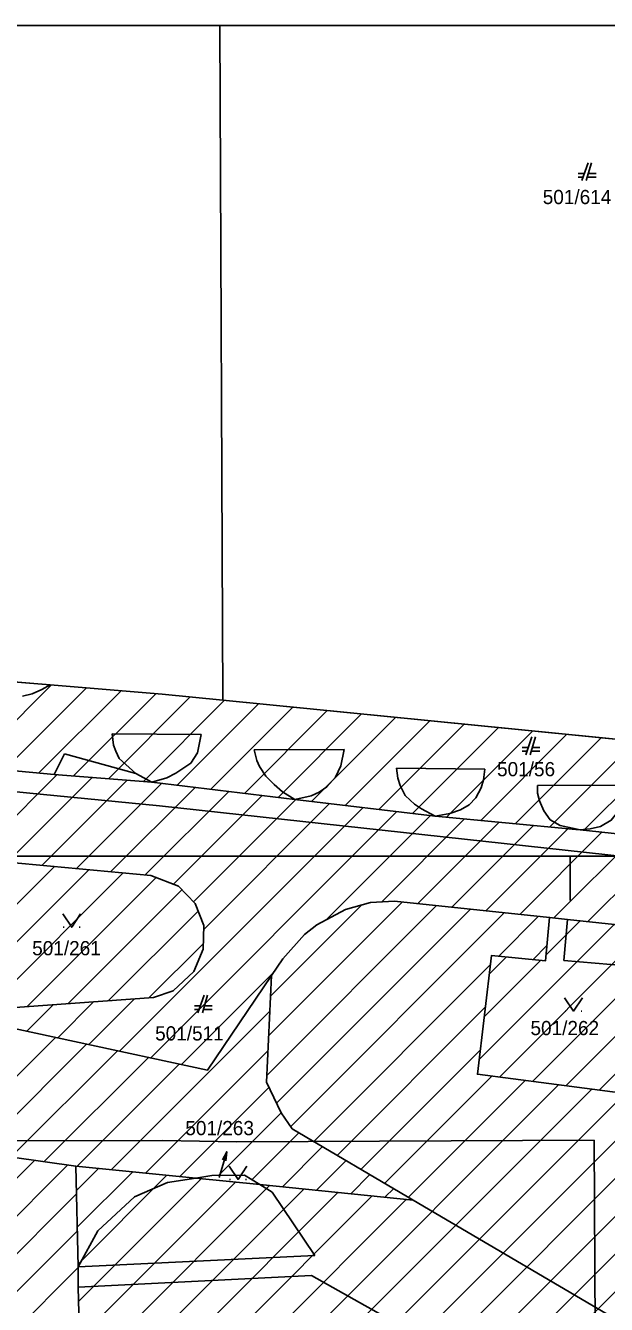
# Model space of a CAD drawing. Extents: x -264309 to -263505, y -1242443 to -1241763.
# Drawn here: x -263852.2 to -263786.7, y -1242101 to -1241957 of the extents above; entities that cross this region are included whole.
import ezdxf

# ---------------------------------------------------------------- set-up
doc = ezdxf.new("R2010")
doc.units = 0
for name, color, linetype in [('KFA_SO_50-2_POZIARNY_VODOVOD_TRASA', 7, 'Continuous'), ('KN_2019_08_16_KLADPAR', 7, 'Continuous'), ('KN_2019_08_16_ZAPPAR', 7, 'Continuous'), ('RAM_NA_TLAC_10xA4_1-500', 7, 'Continuous'), ('SRAFY_PARCELY', 7, 'Continuous')]:
    doc.layers.add(name, color=color, linetype=linetype)

msp = doc.modelspace()

# ---------------------------------------------------------------- linework, layer by layer
at = {"layer": 'KFA_SO_50-2_POZIARNY_VODOVOD_TRASA'}
msp.add_lwpolyline([(-263924.93, -1242185.13), (-263924.15, -1242197.09), (-263924.3, -1242220.9), (-263924.1, -1242250.12), (-263913.99, -1242249.8), (-263886.91, -1242249.88), (-263867.71, -1242249.83), (-263837.26, -1242249.84), (-263828.16, -1242249.9), (-263787.99, -1242250.03), (-263788.2, -1242220.84), (-263788.2, -1242200.51), (-263788.09, -1242179.92), (-263788.06, -1242148.96), (-263787.92, -1242127.95), (-263787.95, -1242110.97), (-263788.13, -1242082.54), (-263828.43, -1242082.72), (-263836.78, -1242082.56), (-263867.31, -1242082.61), (-263886.71, -1242082.47), (-263924.08, -1242082.61), (-263924.64, -1242106.32), (-263924.48, -1242117.43)], close=True, dxfattribs=at)
at = {"layer": 'KN_2019_08_16_KLADPAR'}
for p, q in [((-263914.3, -1241956.96), (-263830.29, -1241956.96)), ((-263830.29, -1241956.96), (-263829.96, -1242032.95)), ((-263830.29, -1241956.96), (-263745.67, -1241956.96)), ((-263829.96, -1242032.95), (-263830.29, -1241956.96)), ((-263788.8, -1241972.42), (-263789.5, -1241974.42)), ((-263789, -1241974.42), (-263788.4, -1241972.42)), ((-263789.22, -1241973.62), (-263789.9, -1241973.62)), ((-263789.9, -1241974.02), (-263789.36, -1241974.02)), ((-263788.88, -1241974.02), (-263787.9, -1241974.02)), ((-263787.9, -1241973.62), (-263788.76, -1241973.62)), ((-263849.43, -1242031.23), (-263857.26, -1242030.58)), ((-263836.79, -1242032.27), (-263849.43, -1242031.23)), ((-263829.96, -1242032.95), (-263836.79, -1242032.27)), ((-263750.04, -1242040.89), (-263829.96, -1242032.95)), ((-263795.54, -1242038.3), (-263796.22, -1242038.3)), ((-263795.12, -1242037.1), (-263795.82, -1242039.1)), ((-263795.32, -1242039.1), (-263794.72, -1242037.1)), ((-263794.22, -1242038.3), (-263795.08, -1242038.3)), ((-263796.22, -1242038.7), (-263795.68, -1242038.7)), ((-263795.2, -1242038.7), (-263794.22, -1242038.7)), ((-263847.95, -1242058.55), (-263847.85, -1242058.55)), ((-263846.15, -1242058.55), (-263846.05, -1242058.55)), ((-263832.08, -1242066.2), (-263832.78, -1242068.2)), ((-263832.28, -1242068.2), (-263831.68, -1242066.2)), ((-263832.5, -1242067.4), (-263833.18, -1242067.4)), ((-263833.18, -1242067.8), (-263832.64, -1242067.8)), ((-263832.16, -1242067.8), (-263831.18, -1242067.8)), ((-263831.18, -1242067.4), (-263832.04, -1242067.4)), ((-263791.39, -1242067.99), (-263791.29, -1242067.99)), ((-263789.59, -1242067.99), (-263789.49, -1242067.99)), ((-263830, -1242084.75), (-263829.53, -1242083.84)), ((-263829.2, -1242086.95), (-263829.1, -1242086.95)), ((-263827.4, -1242086.95), (-263827.3, -1242086.95))]:
    msp.add_line(p, q, dxfattribs=at)
for points in [[(-263773.94, -1242049.27), (-263789.68, -1242047.57), (-263790.18, -1242047.53), (-263806.03, -1242046.03), (-263821.84, -1242044.14), (-263837.98, -1242042.2), (-263848.99, -1242041.32), (-263854.22, -1242040.83), (-263895.14, -1242037.44), (-263924.96, -1242034.66), (-263926.48, -1242034.52), (-263943.42, -1242032.17), (-263943.43, -1242031.76), (-263943.61, -1242023.45), (-263914.84, -1242025.82), (-263914, -1242025.89), (-263874.62, -1242029.15), (-263857.26, -1242030.58), (-263849.43, -1242031.23), (-263836.79, -1242032.27), (-263829.96, -1242032.95), (-263750.04, -1242040.89)], [(-263970.71, -1242028.65), (-263951.74, -1242030.76), (-263946.18, -1242031.43), (-263943.43, -1242031.76), (-263943.42, -1242032.17), (-263926.48, -1242034.52), (-263924.96, -1242034.66), (-263895.14, -1242037.44), (-263854.22, -1242040.83), (-263848.99, -1242041.32), (-263837.98, -1242042.2), (-263821.84, -1242044.14), (-263806.03, -1242046.03), (-263790.18, -1242047.53), (-263789.68, -1242047.57), (-263773.94, -1242049.27)], [(-263784.04, -1242058.41), (-263791.13, -1242057.66), (-263793.14, -1242057.44), (-263810.6, -1242055.59), (-263813.32, -1242055.74), (-263816.16, -1242056.54), (-263819.37, -1242058.28), (-263820.78, -1242059.35), (-263823.22, -1242062.1), (-263824.48, -1242063.97), (-263831.68, -1242074.63), (-263861.71, -1242068.19), (-263837.8, -1242066.47), (-263835.57, -1242065.69), (-263833.22, -1242063.52), (-263832.17, -1242061), (-263832.11, -1242058.36), (-263833.09, -1242055.88), (-263834.98, -1242053.91), (-263838.09, -1242052.7), (-263860.75, -1242050.61)], [(-263845.63, -1242123.54), (-263846.29, -1242099.09), (-263846.27, -1242096.79), (-263846.54, -1242085.45), (-263833.02, -1242086.81), (-263825.79, -1242087.54), (-263808.5, -1242089.28), (-263822.15, -1242081.25), (-263823.41, -1242079.44), (-263825.06, -1242076), (-263824.48, -1242063.97), (-263823.22, -1242062.1), (-263820.78, -1242059.35), (-263819.37, -1242058.28), (-263816.16, -1242056.54), (-263813.32, -1242055.74), (-263810.6, -1242055.59), (-263793.14, -1242057.44), (-263793.59, -1242062.32), (-263799.68, -1242061.72), (-263801.28, -1242075.1), (-263785.17, -1242077.19)], [(-263848, -1242057.05), (-263847, -1242058.55), (-263846, -1242057.05)], [(-263791.44, -1242066.49), (-263790.44, -1242067.99), (-263789.44, -1242066.49)], [(-263830.38, -1242086.72), (-263829.53, -1242083.84), (-263829.62, -1242084.86)], [(-263829.25, -1242085.45), (-263828.25, -1242086.95), (-263827.25, -1242085.45)]]:
    msp.add_lwpolyline(points, dxfattribs=at)
for points in [[(-263860.75, -1242050.61), (-263838.09, -1242052.7), (-263834.98, -1242053.91), (-263833.09, -1242055.88), (-263832.11, -1242058.36), (-263832.17, -1242061), (-263833.22, -1242063.52), (-263835.57, -1242065.69), (-263837.8, -1242066.47), (-263861.71, -1242068.19), (-263866.84, -1242068.34), (-263856.75, -1242052.73), (-263857.2, -1242052.16), (-263859.25, -1242051.26)], [(-263793.14, -1242057.44), (-263791.13, -1242057.66), (-263784.04, -1242058.41), (-263782.02, -1242058.63), (-263782.64, -1242063.41), (-263775.43, -1242063.83), (-263775.63, -1242071.05), (-263780.92, -1242070.3), (-263781.45, -1242072.38), (-263784.12, -1242072.3), (-263785.17, -1242077.19), (-263801.28, -1242075.1), (-263799.68, -1242061.72), (-263793.59, -1242062.32)], [(-263866.84, -1242068.34), (-263861.71, -1242068.19), (-263831.68, -1242074.63), (-263824.48, -1242063.97), (-263825.06, -1242076), (-263823.41, -1242079.44), (-263822.15, -1242081.25), (-263808.5, -1242089.28), (-263825.79, -1242087.54), (-263827.51, -1242086.49), (-263831.22, -1242086.53), (-263833.02, -1242086.81), (-263846.54, -1242085.45), (-263942.54, -1242071.9), (-263913.4, -1242070.43), (-263886.83, -1242069.14)], [(-263942.54, -1242071.9), (-263846.54, -1242085.45), (-263846.27, -1242096.79), (-263846.29, -1242099.09), (-263845.63, -1242123.54), (-263845.17, -1242145.54), (-263890.62, -1242146.65), (-263890.76, -1242147.37), (-263921.62, -1242147.75), (-263934.65, -1242147.91), (-263935.23, -1242123.81), (-263941.18, -1242123.7)], [(-263833.02, -1242086.81), (-263831.22, -1242086.53), (-263827.51, -1242086.49), (-263825.79, -1242087.54)]]:
    msp.add_lwpolyline(points, close=True, dxfattribs=at)
at = {"layer": 'KN_2019_08_16_ZAPPAR'}
for p, q in [((-263842.44, -1242036.74), (-263832.41, -1242036.83)), ((-263848.99, -1242041.32), (-263847.83, -1242039)), ((-263847.83, -1242039), (-263839.79, -1242041.23)), ((-263826.44, -1242038.56), (-263816.28, -1242038.5)), ((-263810.4, -1242040.62), (-263800.44, -1242040.72)), ((-263794.51, -1242042.59), (-263784.38, -1242042.55)), ((-263837.1, -1242044.85), (-263784.51, -1242050.62)), ((-263791.13, -1242057.66), (-263791.54, -1242062.3)), ((-263791.54, -1242062.3), (-263784.47, -1242062.88)), ((-263844.07, -1242092.73), (-263839.91, -1242088.93)), ((-263808.5, -1242089.28), (-263779.5, -1242106.34)), ((-263846.27, -1242096.79), (-263844.07, -1242092.73)), ((-263819.59, -1242095.53), (-263846.27, -1242096.79))]:
    msp.add_line(p, q, dxfattribs=at)
for points in [[(-264009.05, -1242025.11), (-264007.06, -1242027.03), (-264004.88, -1242027.82), (-264001.52, -1242027.99), (-263958.32, -1242033), (-263951.68, -1242033.75), (-263943.48, -1242034.79), (-263940.72, -1242035.02), (-263926.91, -1242036.98), (-263897.04, -1242039.59), (-263857.13, -1242042.91), (-263837.1, -1242044.85)], [(-263849.43, -1242031.23), (-263850.37, -1242031.77), (-263851.47, -1242032.24), (-263852.57, -1242032.52)], [(-263839.79, -1242041.23), (-263841.67, -1242039.55), (-263842.02, -1242038.7), (-263842.29, -1242038.02), (-263842.44, -1242036.74)], [(-263832.41, -1242036.83), (-263832.83, -1242038.89), (-263833.57, -1242040.05), (-263835.28, -1242041.18), (-263836.28, -1242041.7), (-263837.98, -1242042.2), (-263839.79, -1242041.23)], [(-263821.84, -1242044.14), (-263823.25, -1242043.3), (-263824.18, -1242042.46), (-263825.11, -1242041.53), (-263825.82, -1242040.45), (-263826.13, -1242039.75), (-263826.44, -1242038.56)], [(-263816.28, -1242038.5), (-263816.67, -1242040.36), (-263817.26, -1242041.62), (-263818.26, -1242042.72), (-263819.1, -1242043.33), (-263820.01, -1242043.75), (-263821.84, -1242044.14)], [(-263800.44, -1242040.72), (-263800.6, -1242041.94), (-263800.86, -1242042.85), (-263801.46, -1242043.97), (-263802.2, -1242044.75), (-263803.16, -1242045.33), (-263804.37, -1242045.72), (-263806.03, -1242046.03), (-263807.58, -1242045.2), (-263808.35, -1242044.69), (-263808.86, -1242044.23), (-263809.41, -1242043.71), (-263809.99, -1242042.56), (-263810.25, -1242041.75), (-263810.4, -1242040.62)], [(-263789.68, -1242047.57), (-263791.94, -1242047.07), (-263793.07, -1242046.43), (-263793.8, -1242045.41), (-263794.29, -1242044.29), (-263794.49, -1242043.45), (-263794.51, -1242042.59)], [(-263784.38, -1242042.55), (-263784.64, -1242044.03), (-263785.09, -1242045.11), (-263786.18, -1242046.49), (-263787.4, -1242047.18), (-263788.56, -1242047.44), (-263789.68, -1242047.57)], [(-263839.91, -1242088.93), (-263836.21, -1242087.31), (-263833.02, -1242086.81)], [(-263825.79, -1242087.54), (-263824.41, -1242088.38), (-263819.59, -1242095.53)], [(-263846.29, -1242099.09), (-263819.98, -1242097.79), (-263807.62, -1242104.72), (-263808.64, -1242106.7), (-263804.15, -1242109.21), (-263803.06, -1242107.29)]]:
    msp.add_lwpolyline(points, dxfattribs=at)
at = {"layer": 'RAM_NA_TLAC_10xA4_1-500'}
msp.add_line((-263790.83, -1242050.54), (-263790.83, -1242055.54), dxfattribs=at)
msp.add_lwpolyline([(-264210.83, -1242050.54), (-264105.83, -1242050.54), (-264000.83, -1242050.54), (-263895.83, -1242050.54), (-263790.83, -1242050.54), (-263685.83, -1242050.54), (-263685.83, -1242199.04), (-263685.83, -1242347.54), (-263790.83, -1242347.54), (-263895.83, -1242347.54), (-264000.83, -1242347.54), (-264105.83, -1242347.54), (-264210.83, -1242347.54), (-264210.83, -1242199.04)], close=True, dxfattribs=at)
at = {"layer": 'SRAFY_PARCELY'}
for p, q in [((-263858.5, -1242040.48), (-263849.27, -1242031.24)), ((-263854.58, -1242040.8), (-263845.35, -1242031.57)), ((-263850.7, -1242041.16), (-263841.43, -1242031.89)), ((-263846.79, -1242041.5), (-263837.5, -1242032.21)), ((-263842.86, -1242041.81), (-263833.64, -1242032.58)), ((-263838.93, -1242042.12), (-263829.78, -1242032.97)), ((-263835.11, -1242042.54), (-263825.92, -1242033.35)), ((-263831.32, -1242043), (-263822.06, -1242033.74)), ((-263827.54, -1242043.46), (-263818.2, -1242034.12)), ((-263823.75, -1242043.91), (-263814.34, -1242034.5)), ((-263819.96, -1242044.36), (-263810.48, -1242034.89)), ((-263816.17, -1242044.82), (-263806.62, -1242035.27)), ((-263812.38, -1242045.27), (-263802.76, -1242035.65)), ((-263808.59, -1242045.72), (-263798.9, -1242036.04)), ((-263804.77, -1242046.15), (-263795.04, -1242036.42)), ((-263800.9, -1242046.52), (-263791.18, -1242036.8)), ((-263797.02, -1242046.88), (-263787.33, -1242037.19)), ((-263793.15, -1242047.25), (-263783.47, -1242037.57)), ((-263789.27, -1242047.61), (-263779.61, -1242037.95)), ((-263858.13, -1242050.85), (-263848.63, -1242041.35)), ((-263854.25, -1242051.21), (-263844.7, -1242041.66)), ((-263850.36, -1242051.57), (-263840.77, -1242041.98)), ((-263846.48, -1242051.93), (-263836.88, -1242042.33)), ((-263842.59, -1242052.28), (-263833.09, -1242042.79)), ((-263838.71, -1242052.64), (-263829.31, -1242043.24)), ((-263835.52, -1242053.7), (-263825.52, -1242043.7)), ((-263833.27, -1242055.69), (-263821.73, -1242044.15)), ((-263841.6, -1242072.5), (-263814.15, -1242045.06)), ((-263838.1, -1242073.25), (-263810.36, -1242045.51)), ((-263832.12, -1242058.78), (-263817.94, -1242044.61)), ((-263818.32, -1242057.71), (-263806.57, -1242045.96)), ((-263812.04, -1242055.67), (-263802.71, -1242046.34)), ((-263807.99, -1242055.87), (-263798.83, -1242046.71)), ((-263804.15, -1242056.27), (-263794.96, -1242047.08)), ((-263800.32, -1242056.68), (-263791.08, -1242047.44)), ((-263796.48, -1242057.09), (-263787.23, -1242047.83)), ((-263792.65, -1242057.49), (-263783.4, -1242048.25)), ((-263788.82, -1242057.9), (-263779.57, -1242048.66)), ((-263865.56, -1242068.3), (-263848.95, -1242051.7)), ((-263861.16, -1242068.15), (-263845.07, -1242052.06)), ((-263856.59, -1242067.82), (-263841.19, -1242052.41)), ((-263852.02, -1242067.49), (-263837.47, -1242052.94)), ((-263847.45, -1242067.16), (-263834.6, -1242054.31)), ((-263824.81, -1242070.78), (-263809.72, -1242055.68)), ((-263842.88, -1242066.84), (-263832.76, -1242056.72)), ((-263825.02, -1242075.23), (-263805.88, -1242056.09)), ((-263824.59, -1242066.32), (-263814.29, -1242056.01)), ((-263823.92, -1242078.37), (-263802.04, -1242056.5)), ((-263822.32, -1242081.01), (-263798.21, -1242056.9)), ((-263801.08, -1242073.46), (-263785.84, -1242058.22)), ((-263798.86, -1242061.8), (-263794.37, -1242057.31)), ((-263793.53, -1242061.66), (-263789.68, -1242057.81)), ((-263798.8, -1242075.42), (-263782.02, -1242058.64)), ((-263845.24, -1242142.12), (-263763.7, -1242060.58)), ((-263844.47, -1242145.59), (-263759.86, -1242060.99)), ((-263840.85, -1242146.22), (-263756.03, -1242061.39)), ((-263838.31, -1242066.51), (-263832.16, -1242060.36)), ((-263795, -1242062.18), (-263793.43, -1242060.61)), ((-263836.6, -1242146.2), (-263752.19, -1242061.8)), ((-263832.27, -1242146.12), (-263748.36, -1242062.21)), ((-263819.73, -1242082.67), (-263799.8, -1242062.74)), ((-263800.51, -1242068.64), (-263794.13, -1242062.27)), ((-263799.93, -1242063.82), (-263798, -1242061.89)), ((-263834.61, -1242074), (-263824.28, -1242063.67)), ((-263795.05, -1242075.91), (-263782.55, -1242063.41)), ((-263791.29, -1242076.4), (-263778.55, -1242063.65)), ((-263848.58, -1242071), (-263844.53, -1242066.95)), ((-263845.09, -1242071.75), (-263839.96, -1242066.63)), ((-263852.08, -1242070.26), (-263849.11, -1242067.28)), ((-263842.53, -1242085.85), (-263824.67, -1242068)), ((-263817.06, -1242084.24), (-263800.38, -1242067.56)), ((-263861.26, -1242083.37), (-263848.84, -1242070.95)), ((-263845.33, -1242137.97), (-263778.07, -1242070.7)), ((-263857.55, -1242083.9), (-263845.35, -1242071.7)), ((-263853.83, -1242084.42), (-263841.85, -1242072.45)), ((-263838.68, -1242086.24), (-263824.89, -1242072.45)), ((-263814.39, -1242085.81), (-263800.95, -1242072.38)), ((-263850.11, -1242084.95), (-263838.36, -1242073.2)), ((-263846.39, -1242085.47), (-263834.87, -1242073.95)), ((-263787.54, -1242076.88), (-263784.44, -1242073.78)), ((-263811.72, -1242087.39), (-263799.65, -1242075.31)), ((-263809.05, -1242088.96), (-263795.89, -1242075.8)), ((-263845.5, -1242129.65), (-263792.13, -1242076.29)), ((-263845.42, -1242133.81), (-263788.38, -1242076.77)), ((-263834.82, -1242086.63), (-263824.78, -1242076.59)), ((-263830.47, -1242086.52), (-263823.4, -1242079.45)), ((-263826.7, -1242086.99), (-263821.4, -1242081.69)), ((-263823.26, -1242087.79), (-263818.73, -1242083.26)), ((-263914.02, -1242147.66), (-263851.17, -1242084.8)), ((-263909.73, -1242147.6), (-263847.45, -1242085.32)), ((-263846.47, -1242088.2), (-263843.98, -1242085.71)), ((-263819.41, -1242088.18), (-263816.06, -1242084.83)), ((-263846.38, -1242092.34), (-263840.13, -1242086.1)), ((-263846.28, -1242096.49), (-263836.27, -1242086.48)), ((-263846.25, -1242100.7), (-263832.42, -1242086.87)), ((-263846.14, -1242104.83), (-263828.56, -1242087.26)), ((-263815.55, -1242088.57), (-263813.39, -1242086.41)), ((-263905.43, -1242147.55), (-263846.47, -1242088.58)), ((-263846.02, -1242108.96), (-263824.71, -1242087.65)), ((-263845.91, -1242113.09), (-263820.85, -1242088.04)), ((-263845.8, -1242117.22), (-263817, -1242088.42)), ((-263845.69, -1242121.36), (-263813.15, -1242088.81)), ((-263811.7, -1242088.96), (-263810.71, -1242087.98)), ((-263845.59, -1242125.5), (-263809.29, -1242089.2)), ((-263901.14, -1242147.5), (-263846.37, -1242092.73)), ((-263896.84, -1242147.44), (-263846.27, -1242096.87))]:
    msp.add_line(p, q, dxfattribs=at)

# ---------------------------------------------------------------- texts
at = {"layer": 'KN_2019_08_16_KLADPAR'}
for s, p in [('501/614', (-263793.91, -1241977.07)), ('501/56', (-263799.06, -1242041.53)), ('501/261', (-263851.46, -1242061.7)), ('501/511', (-263837.6, -1242071.3)), ('501/262', (-263795.29, -1242070.7)), ('501/263', (-263834.2, -1242081.97))]:
    msp.add_text(s, height=1.6, dxfattribs=at).set_placement(p)

doc.saveas('drawing.dxf')
